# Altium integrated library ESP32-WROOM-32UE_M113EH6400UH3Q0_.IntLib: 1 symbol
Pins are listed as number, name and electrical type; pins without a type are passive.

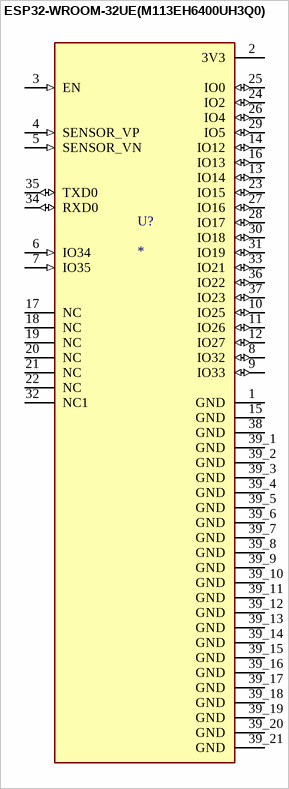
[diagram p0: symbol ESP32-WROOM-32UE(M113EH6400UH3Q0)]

## ESP32-WROOM-32UE(M113EH6400UH3Q0)
designator U?
WiFi Modules (802.11) SMD module ESP32-D0WD-V3, ESP32 ECO V3, 8 MB SPI flash, IPEX antenna connector; MP: ESP32-WROOM-32UE(M113EH6400UH3Q0)
footprint MODULE_ESP32-WROOM-32UE(M113EH6400UH3Q0)
pins: 1 GND (power), 2 3V3 (power), 3 EN (in), 4 SENSOR_VP (in), 5 SENSOR_VN (in), 6 IO34 (in), 7 IO35 (in), 8 IO32 (io), 9 IO33 (io), 10 IO25 (io), 11 IO26 (io), 12 IO27 (io), 13 IO14 (io), 14 IO12 (io), 15 GND (power), 16 IO13 (io), 17 NC, 18 NC, 19 NC, 20 NC, 21 NC, 22 NC, 23 IO15 (io), 24 IO2 (io), 25 IO0 (io), 26 IO4 (io), 27 IO16 (io), 28 IO17 (io), 29 IO5 (io), 30 IO18 (io), 31 IO19 (io), 32 NC1, 33 IO21 (io), 34 RXD0 (io), 35 TXD0 (io), 36 IO22 (io), 37 IO23 (io), 38 GND (power), 39_1 GND (power), 39_2 GND (power), 39_3 GND (power), 39_4 GND (power), 39_5 GND (power), 39_6 GND (power), 39_7 GND (power), 39_8 GND (power), 39_9 GND (power), 39_10 GND (power), 39_11 GND (power), 39_12 GND (power), 39_13 GND (power), 39_14 GND (power), 39_15 GND (power), 39_16 GND (power), 39_17 GND (power), 39_18 GND (power), 39_19 GND (power), 39_20 GND (power), 39_21 GND (power)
